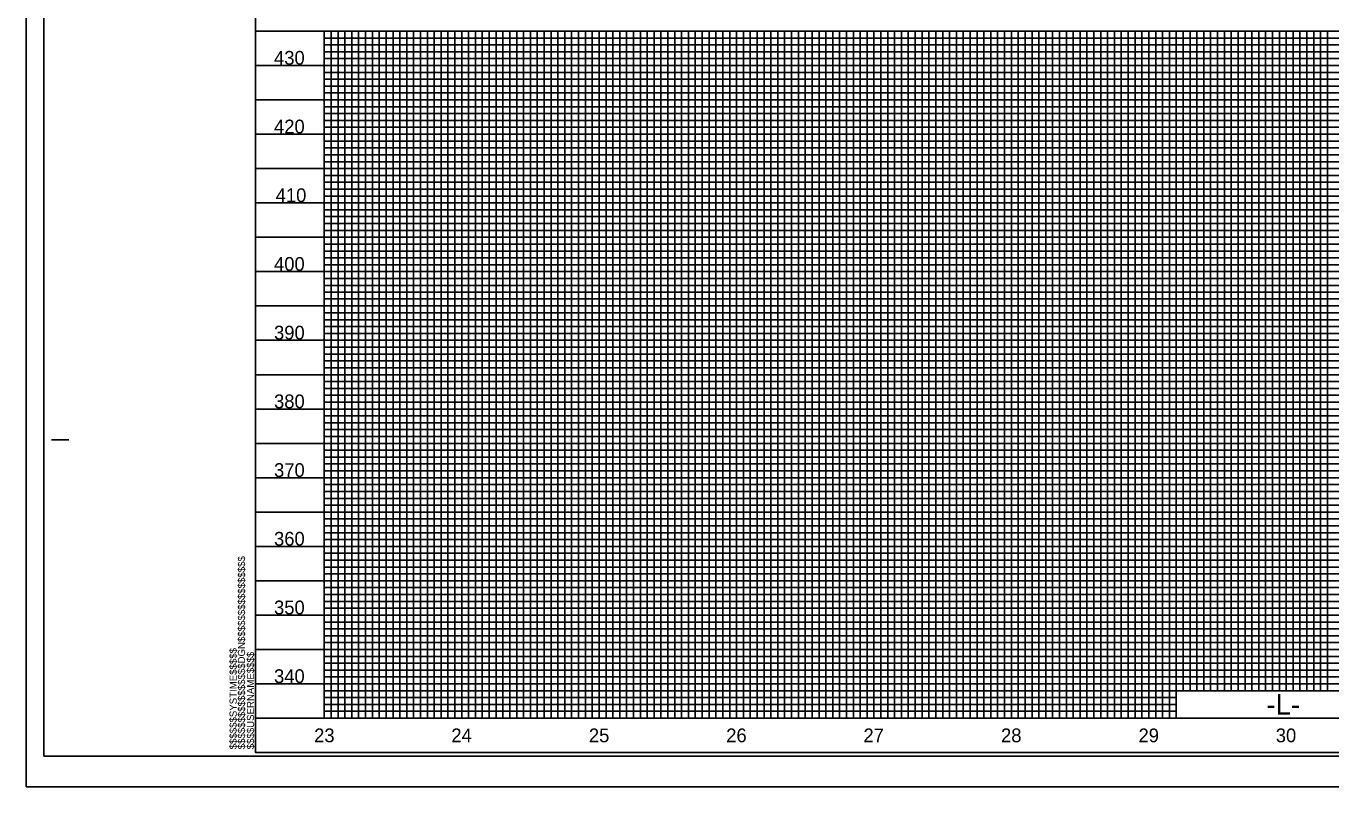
# Model space of a CAD drawing. Extents: x 1629887 to 1632095, y 1174261 to 1175361.
# Drawn here: x 1629887 to 1630837, y 1174261 to 1174814 of the extents above; entities that cross this region are included whole.
import ezdxf

# ---------------------------------------------------------------- set-up
doc = ezdxf.new("R2010")
doc.units = 0
for name, color, linetype in [('Exist Vertical Profile Horizontal Axis Label Major', 7, 'Continuous'), ('Exist Vertical Profile Vertical Axis Label', 7, 'Continuous'), ('Prop Grid Mask', 7, 'Continuous'), ('Sheet Data Field CELL', 7, 'Continuous'), ('Sheet Layout Profile Border Port 2', 7, 'Continuous'), ('Sheet Plan CELL', 7, 'Continuous'), ('Sheet Plot Border Inside CELL', 7, 'Continuous'), ('Sheet Plot Border Outside CELL', 7, 'Continuous'), ('Sheet Profile CELL', 7, 'Continuous'), ('Sheet Profile Grid Major CELL', 7, 'Continuous'), ('Sheet Profile Grid Middle CELL', 7, 'Continuous'), ('Sheet Profile Grid Minor CELL', 7, 'Continuous')]:
    doc.layers.add(name, color=color, linetype=linetype)

msp = doc.modelspace()

# ---------------------------------------------------------------- linework, layer by layer
at = {"layer": 'Prop Grid Mask'}
for points in [[(1630724.31, 1174635.79), (1630799.31, 1174635.79), (1630799.31, 1174590.79), (1630724.31, 1174590.79)], [(1630209.31, 1174550.79), (1630294.31, 1174550.79), (1630294.31, 1174495.79), (1630209.31, 1174495.79)]]:
    msp.add_lwpolyline(points, close=True, dxfattribs=at)
at = {"layer": 'Sheet Data Field CELL'}
msp.add_lwpolyline([(1630724.31, 1174310.79), (1630884.31, 1174310.79), (1630884.31, 1174330.79), (1630724.31, 1174330.79)], close=True, dxfattribs=at)
at = {"layer": 'Sheet Layout Profile Border Port 2'}
msp.add_lwpolyline([(1630104.31, 1174810.79), (1631504.31, 1174810.79), (1631504.31, 1174335.79), (1631304.31, 1174335.79), (1631304.31, 1174310.79), (1630884.31, 1174310.79), (1630884.31, 1174330.79), (1630724.31, 1174330.79), (1630724.31, 1174310.79), (1630104.31, 1174310.79)], close=True, dxfattribs=at)
at = {"layer": 'Sheet Plot Border Inside CELL'}
msp.add_lwpolyline([(1629900.31, 1174283.24), (1631566.81, 1174283.24), (1631566.81, 1175338.34), (1629900.31, 1175338.34)], close=True, dxfattribs=at)
at = {"layer": 'Sheet Plot Border Outside CELL'}
msp.add_lwpolyline([(1629887.31, 1174260.79), (1631571.31, 1174260.79), (1631571.31, 1175360.79), (1629887.31, 1175360.79)], close=True, dxfattribs=at)
at = {"layer": 'Sheet Profile CELL'}
for p, q in [((1630054.31, 1174810.79), (1631554.31, 1174810.79)), ((1629905.81, 1174513.29), (1629918.31, 1174513.29)), ((1631554.31, 1174310.79), (1630054.31, 1174310.79)), ((1630054.31, 1174285.79), (1631554.31, 1174285.79)), ((1630054.31, 1174285.79), (1630054.31, 1174285.79)), ((1630054.31, 1174285.79), (1630054.31, 1174285.79)), ((1630054.31, 1174285.79), (1630054.31, 1174285.79)), ((1630054.31, 1174285.79), (1630054.31, 1174285.79)), ((1630054.31, 1174285.79), (1630054.31, 1174285.79)), ((1630054.31, 1174285.79), (1630054.31, 1174285.79)), ((1630054.31, 1174285.79), (1630054.31, 1174285.79))]:
    msp.add_line(p, q, dxfattribs=at)
msp.add_lwpolyline([(1631554.31, 1175335.79), (1630054.31, 1175335.79), (1630054.31, 1174285.79), (1631554.31, 1174285.79)], close=True, dxfattribs=at)
msp.add_lwpolyline([(1630091.81, 1174285.79), (1630091.81, 1174285.79)], dxfattribs=at)
at = {"layer": 'Sheet Profile Grid Major CELL'}
for p, q in [((1630104.31, 1174810.79), (1630104.31, 1174310.79)), ((1630154.31, 1174310.79), (1630154.31, 1174810.79)), ((1630154.31, 1174810.79), (1630204.31, 1174810.79)), ((1630204.31, 1174810.79), (1630204.31, 1174310.79)), ((1630254.31, 1174310.79), (1630254.31, 1174810.79)), ((1630254.31, 1174810.79), (1630304.31, 1174810.79)), ((1630304.31, 1174810.79), (1630304.31, 1174310.79)), ((1630354.31, 1174310.79), (1630354.31, 1174810.79)), ((1630354.31, 1174810.79), (1630404.31, 1174810.79)), ((1630404.31, 1174810.79), (1630404.31, 1174310.79)), ((1630454.31, 1174310.79), (1630454.31, 1174810.79)), ((1630454.31, 1174810.79), (1630504.31, 1174810.79)), ((1630504.31, 1174810.79), (1630504.31, 1174310.79)), ((1630554.31, 1174810.79), (1630604.31, 1174810.79)), ((1630554.31, 1174310.79), (1630554.31, 1174810.79)), ((1630554.31, 1174810.79), (1630604.31, 1174810.79)), ((1630604.31, 1174810.79), (1630604.31, 1174310.79)), ((1630654.31, 1174810.79), (1630704.31, 1174810.79)), ((1630654.31, 1174310.79), (1630654.31, 1174810.79)), ((1630654.31, 1174810.79), (1630704.31, 1174810.79)), ((1630704.31, 1174810.79), (1630704.31, 1174310.79)), ((1630754.31, 1174810.79), (1630804.31, 1174810.79)), ((1630754.31, 1174330.79), (1630754.31, 1174810.79)), ((1630754.31, 1174810.79), (1630804.31, 1174810.79)), ((1630804.31, 1174810.79), (1630804.31, 1174330.79)), ((1630054.31, 1174310.79), (1630054.31, 1174310.79)), ((1630104.31, 1174310.79), (1630154.31, 1174310.79)), ((1630204.31, 1174310.79), (1630254.31, 1174310.79)), ((1630304.31, 1174310.79), (1630354.31, 1174310.79)), ((1630404.31, 1174310.79), (1630454.31, 1174310.79)), ((1630504.31, 1174310.79), (1630554.31, 1174310.79)), ((1630604.31, 1174310.79), (1630654.31, 1174310.79)), ((1630704.31, 1174310.79), (1630734.31, 1174310.79))]:
    msp.add_line(p, q, dxfattribs=at)
for points in [[(1631554.31, 1174785.79), (1630054.31, 1174785.79)], [(1631554.31, 1174735.79), (1630054.31, 1174735.79)], [(1631554.31, 1174685.79), (1630054.31, 1174685.79), (1630054.31, 1174635.79), (1631554.31, 1174635.79)], [(1631554.31, 1174585.79), (1630054.31, 1174585.79), (1630054.31, 1174535.79), (1631554.31, 1174535.79)], [(1631554.31, 1174485.79), (1630054.31, 1174485.79), (1630054.31, 1174435.79), (1631554.31, 1174435.79)], [(1631554.31, 1174385.79), (1630054.31, 1174385.79), (1630054.31, 1174385.79), (1630054.31, 1174335.79), (1631554.31, 1174335.79)], [(1631554.31, 1174310.79), (1630054.31, 1174310.79)]]:
    msp.add_lwpolyline(points, dxfattribs=at)
at = {"layer": 'Sheet Profile Grid Middle CELL'}
for p, q in [((1630779.31, 1174330.79), (1630779.31, 1174810.79)), ((1630779.31, 1174810.79), (1630829.31, 1174810.79)), ((1630829.31, 1174810.79), (1630829.31, 1174330.79))]:
    msp.add_line(p, q, dxfattribs=at)
for points in [[(1630079.31, 1174810.79), (1630129.31, 1174810.79), (1630129.31, 1174310.79), (1630179.31, 1174310.79), (1630179.31, 1174810.79), (1630229.31, 1174810.79), (1630229.31, 1174310.79), (1630279.31, 1174310.79), (1630279.31, 1174810.79), (1630329.31, 1174810.79), (1630329.31, 1174310.79), (1630379.31, 1174310.79), (1630379.31, 1174810.79), (1630429.31, 1174810.79), (1630429.31, 1174310.79), (1630479.31, 1174310.79), (1630479.31, 1174810.79), (1630529.31, 1174810.79), (1630529.31, 1174310.79), (1630579.31, 1174310.79), (1630579.31, 1174810.79), (1630629.31, 1174810.79), (1630629.31, 1174310.79), (1630679.31, 1174310.79), (1630679.31, 1174310.79), (1630679.31, 1174810.79), (1630729.31, 1174810.79), (1630729.31, 1174330.79)], [(1630054.31, 1174760.79), (1631554.31, 1174760.79)], [(1631554.31, 1174710.79), (1630054.31, 1174710.79), (1630054.31, 1174660.79), (1631554.31, 1174660.79)], [(1631554.31, 1174610.79), (1630054.31, 1174610.79), (1630054.31, 1174560.79), (1631554.31, 1174560.79)], [(1631554.31, 1174510.79), (1630054.31, 1174510.79), (1630054.31, 1174460.79), (1631554.31, 1174460.79)], [(1631554.31, 1174410.79), (1630054.31, 1174410.79), (1630054.31, 1174360.79), (1631554.31, 1174360.79)], [(1631554.31, 1174310.79), (1630054.31, 1174310.79)]]:
    msp.add_lwpolyline(points, dxfattribs=at)
at = {"layer": 'Sheet Profile Grid Minor CELL'}
for p, q in [((1630634.31, 1174810.79), (1630634.31, 1174310.79)), ((1630639.31, 1174310.79), (1630639.31, 1174810.79)), ((1630639.31, 1174810.79), (1630644.31, 1174810.79)), ((1630644.31, 1174810.79), (1630644.31, 1174310.79)), ((1630649.31, 1174310.79), (1630649.31, 1174810.79)), ((1630649.31, 1174810.79), (1630659.31, 1174810.79)), ((1630659.31, 1174810.79), (1630659.31, 1174310.79)), ((1630664.31, 1174310.79), (1630664.31, 1174810.79)), ((1630664.31, 1174810.79), (1630669.31, 1174810.79)), ((1630669.31, 1174810.79), (1630669.31, 1174310.79)), ((1630674.31, 1174310.79), (1630674.31, 1174810.79)), ((1630674.31, 1174810.79), (1630684.31, 1174810.79)), ((1630684.31, 1174810.79), (1630684.31, 1174310.79)), ((1630689.31, 1174310.79), (1630689.31, 1174810.79)), ((1630689.31, 1174810.79), (1630694.31, 1174810.79)), ((1630694.31, 1174810.79), (1630694.31, 1174310.79)), ((1630699.31, 1174310.79), (1630699.31, 1174810.79)), ((1630699.31, 1174810.79), (1630709.31, 1174810.79)), ((1630709.31, 1174810.79), (1630709.31, 1174310.79)), ((1630714.31, 1174310.79), (1630714.31, 1174810.79)), ((1630714.31, 1174810.79), (1630719.31, 1174810.79)), ((1630719.31, 1174810.79), (1630719.31, 1174310.79)), ((1630724.31, 1174310.79), (1630724.31, 1174810.79)), ((1630724.31, 1174810.79), (1630734.31, 1174810.79)), ((1630734.31, 1174810.79), (1630734.31, 1174330.79)), ((1630739.31, 1174330.79), (1630739.31, 1174810.79)), ((1630739.31, 1174810.79), (1630744.31, 1174810.79)), ((1630744.31, 1174810.79), (1630744.31, 1174330.79)), ((1630749.31, 1174330.79), (1630749.31, 1174810.79)), ((1630749.31, 1174810.79), (1630759.31, 1174810.79)), ((1630759.31, 1174810.79), (1630759.31, 1174330.79)), ((1630764.31, 1174330.79), (1630764.31, 1174810.79)), ((1630764.31, 1174810.79), (1630769.31, 1174810.79)), ((1630769.31, 1174810.79), (1630769.31, 1174330.79)), ((1630774.31, 1174330.79), (1630774.31, 1174810.79)), ((1630774.31, 1174810.79), (1630784.31, 1174810.79)), ((1630784.31, 1174810.79), (1630784.31, 1174330.79)), ((1630104.31, 1174805.79), (1631504.31, 1174805.79)), ((1631504.31, 1174800.79), (1630104.31, 1174800.79)), ((1630104.31, 1174795.79), (1631504.31, 1174795.79)), ((1631504.31, 1174790.79), (1630104.31, 1174790.79)), ((1630104.31, 1174780.79), (1631504.31, 1174780.79)), ((1631504.31, 1174775.79), (1630104.31, 1174775.79)), ((1630104.31, 1174770.79), (1631504.31, 1174770.79)), ((1631504.31, 1174765.79), (1630104.31, 1174765.79)), ((1630104.31, 1174755.79), (1631504.31, 1174755.79)), ((1631504.31, 1174750.79), (1630104.31, 1174750.79)), ((1630104.31, 1174745.79), (1631504.31, 1174745.79)), ((1631504.31, 1174740.79), (1630104.31, 1174740.79)), ((1630104.31, 1174730.79), (1631504.31, 1174730.79)), ((1631504.31, 1174725.79), (1630104.31, 1174725.79)), ((1630104.31, 1174720.79), (1631504.31, 1174720.79)), ((1631504.31, 1174715.79), (1630104.31, 1174715.79)), ((1630104.31, 1174705.79), (1631504.31, 1174705.79)), ((1631504.31, 1174700.79), (1630104.31, 1174700.79)), ((1630104.31, 1174695.79), (1631504.31, 1174695.79)), ((1631504.31, 1174690.79), (1630104.31, 1174690.79)), ((1630104.31, 1174680.79), (1631504.31, 1174680.79)), ((1631504.31, 1174675.79), (1630104.31, 1174675.79)), ((1630104.31, 1174670.79), (1631504.31, 1174670.79)), ((1631504.31, 1174665.79), (1630104.31, 1174665.79)), ((1630104.31, 1174655.79), (1631504.31, 1174655.79)), ((1631504.31, 1174650.79), (1630104.31, 1174650.79)), ((1630104.31, 1174645.79), (1631504.31, 1174645.79)), ((1631504.31, 1174640.79), (1630104.31, 1174640.79)), ((1630104.31, 1174630.79), (1631504.31, 1174630.79)), ((1631504.31, 1174625.79), (1630104.31, 1174625.79)), ((1630104.31, 1174620.79), (1631504.31, 1174620.79)), ((1631504.31, 1174615.79), (1630104.31, 1174615.94)), ((1630104.31, 1174605.79), (1631504.31, 1174605.79)), ((1631504.31, 1174600.79), (1630104.31, 1174600.79)), ((1630104.31, 1174595.79), (1631504.31, 1174595.79)), ((1631504.31, 1174590.79), (1630104.31, 1174590.79)), ((1630104.31, 1174580.79), (1631504.31, 1174580.79)), ((1631504.31, 1174575.79), (1630104.31, 1174575.79)), ((1630104.31, 1174570.79), (1631504.31, 1174570.79)), ((1631504.31, 1174565.79), (1630104.31, 1174565.79)), ((1630104.31, 1174555.79), (1631504.31, 1174555.79)), ((1631504.31, 1174550.79), (1630104.31, 1174550.79)), ((1630104.31, 1174545.79), (1631504.31, 1174545.79)), ((1631504.31, 1174540.79), (1630104.31, 1174540.79)), ((1630104.31, 1174530.79), (1631504.31, 1174530.79)), ((1631504.31, 1174525.79), (1630104.31, 1174525.79)), ((1630104.31, 1174520.79), (1631504.31, 1174520.79)), ((1631504.31, 1174515.79), (1630104.31, 1174515.79)), ((1630104.31, 1174505.79), (1631504.31, 1174505.79)), ((1631504.31, 1174500.79), (1630104.31, 1174500.79)), ((1630104.31, 1174495.79), (1631504.31, 1174495.79)), ((1631504.31, 1174490.79), (1630104.31, 1174490.79)), ((1630104.31, 1174480.79), (1631504.31, 1174480.79)), ((1631504.31, 1174475.79), (1630104.31, 1174475.79)), ((1630104.31, 1174470.79), (1631504.31, 1174470.79)), ((1631504.31, 1174465.79), (1630104.31, 1174465.79)), ((1630104.31, 1174455.79), (1631504.31, 1174455.79)), ((1631504.31, 1174450.79), (1630104.31, 1174450.79)), ((1630104.31, 1174445.79), (1631504.31, 1174445.79)), ((1631504.31, 1174440.79), (1630104.31, 1174440.79)), ((1630104.31, 1174430.79), (1631504.31, 1174430.79)), ((1631504.31, 1174425.79), (1630104.31, 1174425.79)), ((1630104.31, 1174420.79), (1631504.31, 1174420.79)), ((1631504.31, 1174415.79), (1630104.31, 1174415.79)), ((1630104.31, 1174405.79), (1631504.31, 1174405.79)), ((1631504.31, 1174400.79), (1630104.31, 1174400.79)), ((1630104.31, 1174395.79), (1631504.31, 1174395.79)), ((1631504.31, 1174390.79), (1630104.31, 1174390.79)), ((1630104.31, 1174380.79), (1631504.31, 1174380.79)), ((1631504.31, 1174375.79), (1630104.31, 1174375.79)), ((1630104.31, 1174370.79), (1631504.31, 1174370.79)), ((1631504.31, 1174365.79), (1630104.31, 1174365.79)), ((1630104.31, 1174355.79), (1631504.31, 1174355.79)), ((1631504.31, 1174350.79), (1630104.31, 1174350.79)), ((1630104.31, 1174345.79), (1631504.31, 1174345.79)), ((1631504.31, 1174340.79), (1630104.31, 1174340.79)), ((1630104.31, 1174330.79), (1631304.31, 1174330.79)), ((1630724.31, 1174325.79), (1630104.31, 1174325.79)), ((1630104.31, 1174320.79), (1630724.31, 1174320.79)), ((1630104.31, 1174315.79), (1630724.31, 1174315.79)), ((1630634.31, 1174310.79), (1630639.31, 1174310.79)), ((1630644.31, 1174310.79), (1630649.31, 1174310.79)), ((1630659.31, 1174310.79), (1630664.31, 1174310.79)), ((1630669.31, 1174310.79), (1630674.31, 1174310.79)), ((1630684.31, 1174310.79), (1630689.31, 1174310.79)), ((1630694.31, 1174310.79), (1630699.31, 1174310.79)), ((1630709.31, 1174310.79), (1630714.31, 1174310.79)), ((1630719.31, 1174310.79), (1630724.31, 1174310.79)), ((1630734.31, 1174310.79), (1630739.31, 1174310.79))]:
    msp.add_line(p, q, dxfattribs=at)
for points in [[(1630104.31, 1174810.79), (1630109.31, 1174810.79), (1630109.31, 1174310.79), (1630114.31, 1174310.79), (1630114.31, 1174810.79), (1630119.31, 1174810.79), (1630119.31, 1174310.79), (1630124.31, 1174310.79), (1630124.31, 1174810.79), (1630134.31, 1174810.79), (1630134.31, 1174310.79), (1630139.31, 1174310.79), (1630139.31, 1174810.79), (1630144.31, 1174810.79), (1630144.31, 1174310.79), (1630149.31, 1174310.79), (1630159.31, 1174310.79), (1630164.31, 1174310.79), (1630164.31, 1174810.79), (1630169.31, 1174810.79), (1630169.31, 1174310.79), (1630174.31, 1174310.79), (1630174.31, 1174810.79), (1630184.31, 1174810.79), (1630184.31, 1174310.79), (1630189.31, 1174310.79), (1630189.31, 1174810.79), (1630194.31, 1174810.79), (1630194.31, 1174310.79), (1630199.31, 1174310.79), (1630199.31, 1174810.79), (1630209.31, 1174810.79), (1630209.31, 1174310.79), (1630214.31, 1174310.79), (1630214.31, 1174810.79), (1630219.31, 1174810.79), (1630219.31, 1174310.79), (1630224.31, 1174310.79), (1630224.31, 1174810.79), (1630234.31, 1174810.79), (1630234.31, 1174310.79), (1630239.31, 1174310.79), (1630239.31, 1174810.79), (1630244.31, 1174810.79), (1630244.31, 1174310.79), (1630249.31, 1174310.79), (1630249.31, 1174810.79), (1630259.31, 1174810.79), (1630259.31, 1174310.79), (1630264.31, 1174310.79), (1630264.31, 1174810.79), (1630269.31, 1174810.79), (1630269.31, 1174310.79), (1630274.31, 1174310.79), (1630274.31, 1174810.79), (1630284.31, 1174810.79), (1630284.31, 1174310.79), (1630289.31, 1174310.79), (1630289.31, 1174810.79), (1630294.31, 1174810.79), (1630294.31, 1174310.79), (1630299.31, 1174310.79), (1630299.31, 1174810.79), (1630309.31, 1174810.79), (1630309.31, 1174310.79), (1630314.31, 1174310.79), (1630314.31, 1174810.79), (1630319.31, 1174810.79), (1630319.31, 1174310.79)], [(1630149.31, 1174310.79), (1630149.31, 1174810.79), (1630159.31, 1174810.79), (1630159.31, 1174310.79)], [(1630319.31, 1174310.79), (1630324.31, 1174310.79), (1630324.31, 1174810.79), (1630334.31, 1174810.79), (1630334.31, 1174310.79), (1630339.31, 1174310.79), (1630339.31, 1174810.79), (1630344.31, 1174810.79), (1630344.31, 1174310.79), (1630349.31, 1174310.79), (1630349.31, 1174810.79), (1630359.31, 1174810.79), (1630359.31, 1174310.79), (1630364.31, 1174310.79), (1630364.31, 1174810.79), (1630369.31, 1174810.79), (1630369.31, 1174310.79), (1630374.31, 1174310.79), (1630374.31, 1174810.79), (1630384.31, 1174810.79), (1630384.31, 1174310.79), (1630389.31, 1174310.79), (1630389.31, 1174810.79), (1630394.31, 1174810.79), (1630394.31, 1174310.79), (1630399.31, 1174310.79), (1630399.31, 1174810.79), (1630409.31, 1174810.79), (1630409.31, 1174310.79), (1630414.31, 1174310.79), (1630414.31, 1174810.79), (1630419.31, 1174810.79), (1630419.31, 1174310.79), (1630424.31, 1174310.79), (1630424.31, 1174810.79), (1630434.31, 1174810.79), (1630434.31, 1174310.79), (1630439.31, 1174310.79), (1630439.31, 1174810.79), (1630444.31, 1174810.79), (1630444.31, 1174310.79), (1630449.31, 1174310.79), (1630449.31, 1174810.79), (1630459.31, 1174810.79), (1630459.31, 1174310.79), (1630464.31, 1174310.79), (1630464.31, 1174810.79), (1630469.31, 1174810.79), (1630469.31, 1174310.79), (1630474.31, 1174310.79), (1630474.31, 1174810.79), (1630484.31, 1174810.79), (1630484.31, 1174310.79), (1630489.31, 1174310.79), (1630489.31, 1174810.79), (1630494.31, 1174810.79), (1630494.31, 1174310.79), (1630499.31, 1174310.79), (1630499.31, 1174810.79), (1630509.31, 1174810.79), (1630509.31, 1174310.79), (1630514.31, 1174310.79), (1630514.31, 1174810.79), (1630519.31, 1174810.79), (1630519.31, 1174310.79), (1630524.31, 1174310.79), (1630524.31, 1174810.79), (1630534.31, 1174810.79), (1630534.31, 1174310.79), (1630539.31, 1174310.79), (1630539.31, 1174810.79), (1630544.31, 1174810.79), (1630544.31, 1174310.79), (1630549.31, 1174310.79), (1630549.31, 1174810.79), (1630559.31, 1174810.79), (1630559.31, 1174310.79), (1630564.31, 1174310.79), (1630564.31, 1174810.79), (1630569.31, 1174810.79), (1630569.31, 1174310.79), (1630574.31, 1174310.79), (1630574.31, 1174810.79), (1630584.31, 1174810.79), (1630584.31, 1174310.79), (1630589.31, 1174310.79), (1630589.31, 1174810.79), (1630594.31, 1174810.79), (1630594.31, 1174310.79), (1630599.31, 1174310.79), (1630599.31, 1174810.79), (1630609.31, 1174810.79), (1630609.31, 1174310.79), (1630614.31, 1174310.79), (1630614.31, 1174810.79), (1630619.31, 1174810.79), (1630619.31, 1174310.79), (1630624.31, 1174310.79), (1630624.31, 1174810.79), (1630634.31, 1174810.79)], [(1630789.31, 1174330.79), (1630789.31, 1174810.79), (1630794.31, 1174810.79), (1630794.31, 1174330.79)], [(1630799.31, 1174330.79), (1630799.31, 1174810.79), (1630809.31, 1174810.79), (1630809.31, 1174330.79)], [(1630814.31, 1174330.79), (1630814.31, 1174810.79), (1630819.31, 1174810.79), (1630819.31, 1174330.79)], [(1630824.31, 1174330.79), (1630824.31, 1174810.79), (1630834.31, 1174810.79), (1630834.31, 1174330.79)]]:
    msp.add_lwpolyline(points, dxfattribs=at)

# ---------------------------------------------------------------- texts
at = {"layer": 'Exist Vertical Profile Horizontal Axis Label Major'}
for s, p in [('23', (1630096.92, 1174293.29)), ('24', (1630196.77, 1174293.29)), ('25', (1630296.86, 1174293.29)), ('26', (1630396.8, 1174293.29)), ('27', (1630496.66, 1174293.29)), ('28', (1630596.78, 1174293.29)), ('29', (1630696.82, 1174293.29)), ('30', (1630796.7, 1174293.29))]:
    msp.add_text(s, height=10, dxfattribs=at).set_placement(p)
at = {"layer": 'Exist Vertical Profile Vertical Axis Label'}
for s, p in [('430', (1630067.75, 1174786.38)), ('420', (1630067.75, 1174736.38)), ('410', (1630068.94, 1174686.38)), ('400', (1630067.75, 1174636.38)), ('390', (1630067.75, 1174586.38)), ('380', (1630067.75, 1174536.38)), ('370', (1630067.75, 1174486.38)), ('360', (1630067.75, 1174436.38)), ('350', (1630067.75, 1174386.38)), ('340', (1630067.75, 1174336.38))]:
    msp.add_text(s, height=10, dxfattribs=at).set_placement(p)
at = {"layer": 'Sheet Data Field CELL'}
msp.add_text('-L-', height=15, rotation=360, dxfattribs=at).set_placement((1630789.88, 1174313.29))
at = {"layer": 'Sheet Plan CELL'}
for s, p in [('$$$$$$$$$$$$$$$$DGN$$$$$$$$$$$$$$$$', (1630046.68, 1174288.15)), ('$$$$$$SYSTIME$$$$$', (1630040.6, 1174288.12)), ('$$$$USERNAME$$$$', (1630053.23, 1174288.16))]:
    msp.add_text(s, height=5.25, rotation=90, dxfattribs=at).set_placement(p)

doc.saveas('drawing.dxf')
